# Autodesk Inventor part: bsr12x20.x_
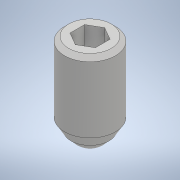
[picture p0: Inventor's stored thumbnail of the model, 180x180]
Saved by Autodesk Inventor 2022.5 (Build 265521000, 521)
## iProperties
Created: 2020-01
Part Number: bsr12x20.x_
Material: 一般
Document SubType Name: Modeling
Designer: ImaoCorp
Density: 1 g/cm^3
Appearance: 既定
Sending System: SOLIDWORKS 2018-2018316
MC: AMD64
MC_MODEL: Intel64 Family 6 Model 60 Stepping 3, GenuineIntel
OS: Windows_NT
FRU: Parasolid Version 30.0, build 310,  6- 8-2018
FORMAT: text
GUISE: transmit
KEY: bsr12x20
FILE: bsr12x20.x_t
DATE: Thu Jan 23 16:48:00 2020
Author: ImaoCorp
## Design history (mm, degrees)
feature "Base1"
node "ソリッド1"
